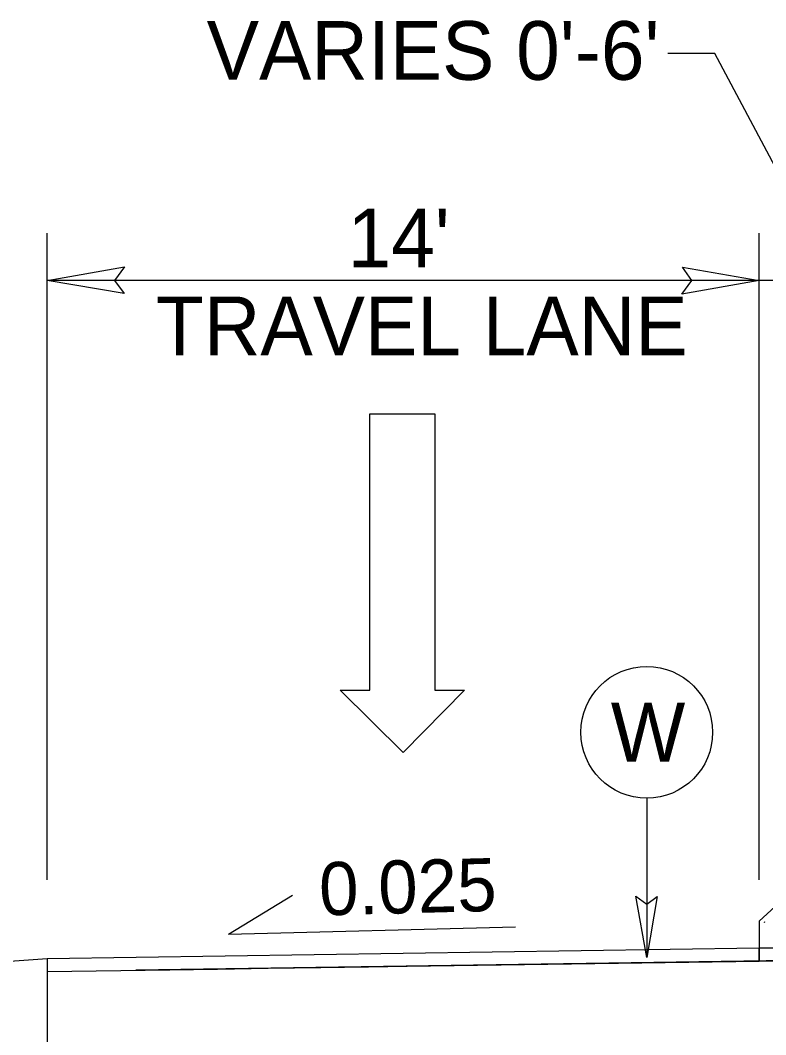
# Model space of a CAD drawing. Extents: x 2176156 to 2177167, y 76401 to 76644.
# Drawn here: x 2176818.63 to 2176833.29, y 76416.24 to 76436.18 of the extents above; entities that cross this region are included whole.
import ezdxf

# ---------------------------------------------------------------- set-up
doc = ezdxf.new("R2010")
doc.units = 0
for name, color, linetype in [('Exist Roads Change in Surface', 7, 'Continuous'), ('Exist Roads Curbs', 7, 'Continuous'), ('Exist Roads Soil', 7, 'Continuous'), ('Exist Structure Minor Culvert Topo', 7, 'Continuous'), ('Exist Structure Minor Drop Inlet', 7, 'Continuous'), ('Exist Utilities Other Pole CELL', 7, 'Continuous'), ('Old_Level_1', 7, 'Continuous'), ('Old_Level_3', 7, 'Continuous'), ('Prop North Arrow NAD83 for Plan Sheets CELL', 7, 'Continuous'), ('Sheet Plan CELL', 7, 'Continuous')]:
    doc.layers.add(name, color=color, linetype=linetype)

msp = doc.modelspace()

# ---------------------------------------------------------------- linework, layer by layer
at = {"layer": 'Exist Roads Change in Surface'}
msp.add_line((2176833.268, 76418.453), (2176833.258, 76418.437), dxfattribs=at)
at = {"layer": 'Exist Roads Curbs'}
for p, q in [((2176833.161, 76417.934), (2176819.161, 76417.726)), ((2176833.161, 76417.934), (2176819.161, 76417.726)), ((2176833.161, 76417.934), (2176835.691, 76417.972)), ((2176834.97, 76417.961), (2176833.161, 76417.934)), ((2176833.161, 76417.684), (2176833.161, 76417.934)), ((2176833.161, 76417.934), (2176833.161, 76417.684)), ((2176819.161, 76417.726), (2176819.161, 76417.476)), ((2176835.019, 76417.712), (2176820.906, 76417.502)), ((2176833.161, 76417.684), (2176835.019, 76417.712)), ((2176819.161, 76417.476), (2176821.569, 76417.512))]:
    msp.add_line(p, q, dxfattribs=at)
msp.add_lwpolyline([(2176821.569, 76417.512), (2176822.509, 76417.526), (2176823.506, 76417.541), (2176824.539, 76417.556), (2176825.48, 76417.57), (2176826.242, 76417.581), (2176833.161, 76417.684)], dxfattribs=at)
at = {"layer": 'Exist Roads Soil'}
for q in [(2176833.556, 76418.829), (2176833.161, 76417.684)]:
    msp.add_line((2176833.161, 76418.465), q, dxfattribs=at)
at = {"layer": 'Exist Structure Minor Drop Inlet'}
for p, q in [((2176825.502, 76423.006), (2176825.502, 76428.438)), ((2176825.502, 76428.438), (2176826.782, 76428.438)), ((2176826.782, 76428.438), (2176826.782, 76423.006)), ((2176826.161, 76421.783), (2176824.92, 76423.006)), ((2176824.92, 76423.006), (2176825.502, 76423.006)), ((2176827.364, 76423.006), (2176826.161, 76421.783)), ((2176826.782, 76423.006), (2176827.364, 76423.006))]:
    msp.add_line(p, q, dxfattribs=at)
at = {"layer": 'Exist Utilities Other Pole CELL'}
for q in [(2176823.982, 76418.98), (2176828.371, 76418.357)]:
    msp.add_line((2176822.726, 76418.21), q, dxfattribs=at)
at = {"layer": 'Old_Level_1'}
for points in [[(2176820.671, 76430.805), (2176819.161, 76431.065), (2176820.679, 76431.333), (2176820.486, 76431.065)], [(2176831.652, 76431.325), (2176833.161, 76431.065), (2176831.643, 76430.796), (2176831.836, 76431.065)]]:
    msp.add_lwpolyline(points, close=True, dxfattribs=at)
at = {"layer": 'Old_Level_3'}
for p, q in [((2176832.287, 76435.525), (2176831.364, 76435.525)), ((2176834.662, 76431.065), (2176832.287, 76435.525)), ((2176819.161, 76419.277), (2176819.161, 76431.992)), ((2176833.161, 76419.277), (2176833.161, 76431.992)), ((2176833.161, 76431.065), (2176819.161, 76431.065)), ((2176844.366, 76431.065), (2176833.161, 76431.065))]:
    msp.add_line(p, q, dxfattribs=at)
at = {"layer": 'Prop North Arrow NAD83 for Plan Sheets CELL'}
msp.add_line((2176830.95, 76420.884), (2176830.95, 76417.751), dxfattribs=at)
msp.add_lwpolyline([(2176831.157, 76418.951), (2176830.95, 76417.751), (2176830.737, 76418.957), (2176830.95, 76418.804)], close=True, dxfattribs=at)
msp.add_circle((2176830.95, 76422.18), 1.296, dxfattribs=at)
at = {"layer": 'Sheet Plan CELL'}
msp.add_line((2176819.161, 76417.476), (2176819.161, 76415.65), dxfattribs=at)
msp.add_lwpolyline([(2176819.161, 76417.726), (2176807.083, 76416.86), (2176801.893, 76416.43), (2176796.742, 76417.165)], dxfattribs=at)

# ---------------------------------------------------------------- texts
at = {"layer": 'Exist Structure Minor Culvert Topo'}
for s, height, p in [("VARIES 0'-6'", 1.15334, (2176822.297, 76435.007)), ("14'", 1.1533, (2176825.067, 76431.324)), ('TRAVEL LANE', 1.15334, (2176821.297, 76429.594))]:
    msp.add_text(s, height=height, dxfattribs=at).set_placement(p)
at = {"layer": 'Exist Utilities Other Pole CELL'}
msp.add_text('0.025', height=1.0429, rotation=1.4932, dxfattribs=at).set_placement((2176824.52, 76418.579))
at = {"layer": 'Prop North Arrow NAD83 for Plan Sheets CELL'}
msp.add_text('W', height=1.16, rotation=0.0003, dxfattribs=at).set_placement((2176830.243, 76421.6))

doc.saveas('drawing.dxf')
